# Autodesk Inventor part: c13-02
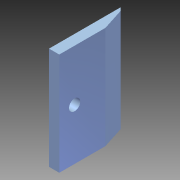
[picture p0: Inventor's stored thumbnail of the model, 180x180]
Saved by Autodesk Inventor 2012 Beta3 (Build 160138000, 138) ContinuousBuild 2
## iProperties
Created: 2010-11
Part Number: c13-02
Material: Default
Document SubType Name: Modeling
Designer: Beta-8540w
Density: 1 g/cm^3
Mass: 58.7997 g
Surface Area: 165.835 cm^2
Volume: 58.7997 cm^3
Author: Beta-8540w
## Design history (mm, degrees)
sketch "Sketch1"
  geometry: L1 (0, 0)-(10, 0); L2 (10, 0)-(10, 70); L3 (10, 70)-(0, 70); L4 (0, 70)-(0, 0); L5 (3, 67)-(10, 45); L6 (0, 70)-(3, 67); 1 further point
  constraints: 12 end point, 2 parallel, 2 point on line, 1 horizontal, 1 perpendicular
  dimensions: "d0" = 10 distance of L3.end L2.end; "d1" = 70 distance of L2.end L1.end; "d3" = 25 vertical distance of point (2.045, 70) L5.end; "d6" = 45 deg angle of L4 L6; "d7" = 3 distance from line of L4 L5.start
extrude "Extrusion1" new body sketch "Sketch1" stored distance "d4" = 100; taper "d5" = 0 deg
hole "Hole1" diameter "d10" = 11; stored, may be unused: countersink angle "d14" = 90 deg, drill point angle "d16" = 118 deg; dims "d8" = 50, "d9" = 15, "d11" = 6, "d12" = 4, "d13" = 2, "d15" = 8
body "Solid1"
